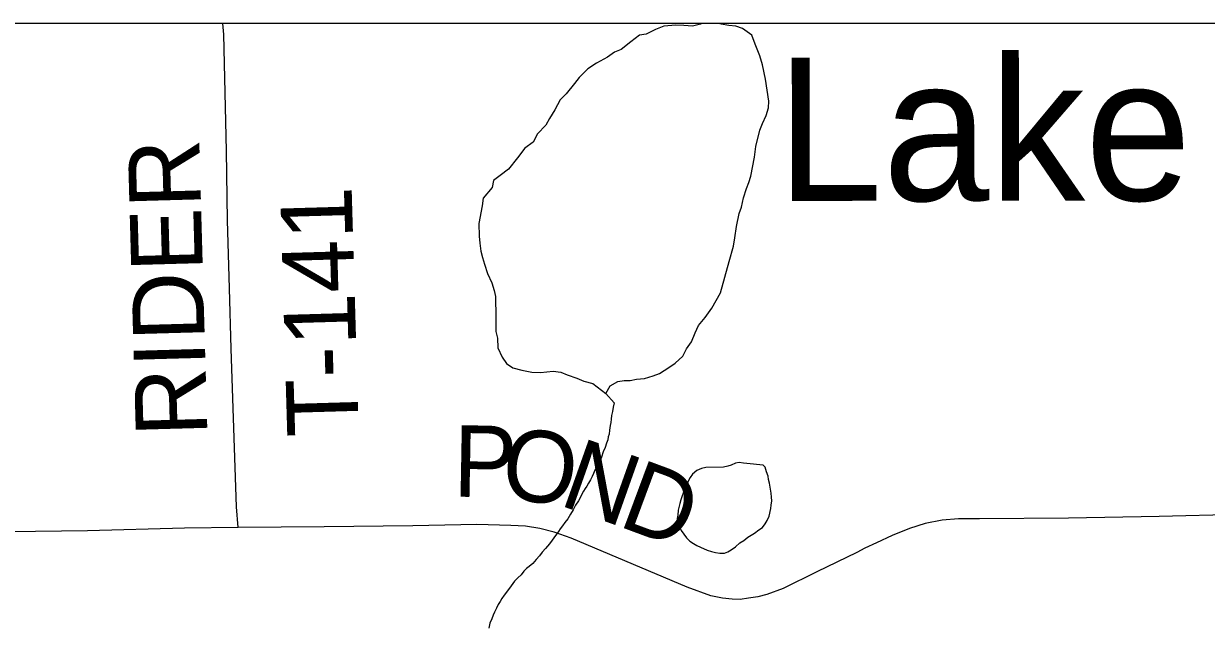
# Model space of a CAD drawing. Extents: x 0 to 34, y 0 to 22.
# Drawn here: x 4.731 to 5.67, y 20.661 to 21.138 of the extents above; entities that cross this region are included whole.
import ezdxf

# ---------------------------------------------------------------- set-up
doc = ezdxf.new("R2010")
doc.units = 0
for name, color, linetype in [('GM_X_County', 7, 'Continuous'), ('GM_X_Minor_Lake', 7, 'Continuous'), ('GM_X_Minor_Lake_Text', 7, 'Continuous'), ('GM_X_Minor_River', 7, 'Continuous'), ('GM_X_Township', 7, 'Continuous'), ('GM_X_Township_Road', 7, 'Continuous'), ('GM_X_Township_Road_Text', 7, 'Continuous')]:
    doc.layers.add(name, color=color, linetype=linetype)

msp = doc.modelspace()

# ---------------------------------------------------------------- linework, layer by layer
at = {"layer": 'GM_X_County'}
msp.add_lwpolyline([(9.16225, 14.34203), (9.16225, 21.13849), (2.36225, 21.13849), (2.36225, 14.33849), (9.00028, 14.33849)], dxfattribs=at)
at = {"layer": 'GM_X_Minor_Lake'}
for points in [[(5.26975, 21.13849), (5.26846, 21.13806), (5.26201, 21.13653), (5.25518, 21.1369), (5.24873, 21.13728), (5.23925, 21.13651), (5.2328, 21.13384), (5.22521, 21.13003), (5.2199, 21.12927), (5.21307, 21.12394), (5.20548, 21.11786), (5.20016, 21.11595), (5.19447, 21.11177), (5.18575, 21.1072), (5.17892, 21.10264), (5.17209, 21.09579), (5.16829, 21.09085), (5.16184, 21.08286), (5.15691, 21.07792), (5.15273, 21.06994), (5.14856, 21.0631), (5.14552, 21.05778), (5.13907, 21.05093), (5.13566, 21.04447), (5.12882, 21.03953), (5.12313, 21.03192), (5.11592, 21.0228), (5.10947, 21.01786), (5.10416, 21.01405), (5.10302, 21.00835), (5.09581, 20.99999), (5.09505, 20.99391), (5.09239, 20.97985), (5.09277, 20.9696), (5.09315, 20.96428), (5.09391, 20.95783), (5.09542, 20.95289), (5.09694, 20.94758), (5.09922, 20.93998), (5.10263, 20.93277), (5.10453, 20.92669), (5.10566, 20.92176), (5.10566, 20.91644), (5.10604, 20.91036), (5.10604, 20.89403), (5.10718, 20.88872), (5.10755, 20.88112), (5.11097, 20.87353), (5.11438, 20.86859), (5.11931, 20.86518), (5.12652, 20.86329), (5.13449, 20.86178), (5.14132, 20.86141), (5.15156, 20.86256), (5.15763, 20.86181), (5.16257, 20.85953), (5.17016, 20.85688), (5.17584, 20.85461), (5.18305, 20.85272), (5.1933, 20.84475)], [(5.21265, 20.85503), (5.21758, 20.85617), (5.22403, 20.85656), (5.23086, 20.85885), (5.23579, 20.86075), (5.24338, 20.86532), (5.24832, 20.86874), (5.25439, 20.87445), (5.25742, 20.88015), (5.26122, 20.88585), (5.26425, 20.89307), (5.26691, 20.89877), (5.27222, 20.90523), (5.27754, 20.91246), (5.28437, 20.92462), (5.2912, 20.94969), (5.29462, 20.96185), (5.29576, 20.96831), (5.2969, 20.97743), (5.29917, 20.98768), (5.30107, 20.99262), (5.30259, 21.00022), (5.30487, 21.00744), (5.30677, 21.01238), (5.30828, 21.01732), (5.31132, 21.03252), (5.31246, 21.04087), (5.3155, 21.05379), (5.31777, 21.05911), (5.32043, 21.06557), (5.32233, 21.07165), (5.32271, 21.07697), (5.32005, 21.09443), (5.31778, 21.10583), (5.3155, 21.11304), (5.31171, 21.12215), (5.30906, 21.12937), (5.30185, 21.13468), (5.29654, 21.13657), (5.29085, 21.13694), (5.28478, 21.13808), (5.28245, 21.13849)], [(5.1933, 20.84475), (5.19671, 20.85084), (5.20278, 20.85426), (5.20772, 20.85503), (5.21265, 20.85503)], [(5.31806, 20.7879), (5.30523, 20.78916), (5.30257, 20.7895), (5.29915, 20.78984), (5.29612, 20.78942), (5.29273, 20.78785), (5.29008, 20.78706), (5.28667, 20.78626), (5.27263, 20.78607), (5.26923, 20.78527), (5.26545, 20.7837), (5.26208, 20.78062), (5.26021, 20.77793), (5.25873, 20.77526), (5.25763, 20.77183), (5.25541, 20.76762), (5.25394, 20.76343), (5.25284, 20.76038), (5.25212, 20.75733), (5.25066, 20.752), (5.25033, 20.7482), (5.24998, 20.74553), (5.25079, 20.74213), (5.25158, 20.73948), (5.25314, 20.73608), (5.25507, 20.73307), (5.25739, 20.73007), (5.26008, 20.72744), (5.26276, 20.72558), (5.26543, 20.7241), (5.26848, 20.72262), (5.27382, 20.72041), (5.27725, 20.71932), (5.2803, 20.7186), (5.28372, 20.71789), (5.28752, 20.71794)], [(5.28752, 20.71794), (5.29016, 20.71911), (5.2928, 20.72067), (5.29618, 20.72299), (5.29956, 20.72607), (5.30295, 20.72801), (5.30595, 20.73071), (5.31123, 20.73382), (5.31461, 20.73652), (5.31762, 20.73846), (5.31987, 20.74114), (5.32135, 20.74382), (5.32283, 20.74725), (5.32427, 20.75335), (5.32462, 20.75601), (5.32495, 20.75943), (5.32491, 20.76247), (5.3245, 20.7655), (5.32326, 20.77345), (5.32247, 20.77648), (5.32205, 20.77913), (5.32087, 20.78253), (5.31969, 20.78631), (5.31806, 20.7879)]]:
    msp.add_lwpolyline(points, dxfattribs=at)
at = {"layer": 'GM_X_Minor_River'}
msp.add_lwpolyline([(5.1933, 20.84475), (5.19987, 20.83733), (5.19918, 20.8339), (5.19849, 20.83047), (5.1978, 20.82741), (5.19748, 20.82436), (5.19716, 20.8217), (5.19683, 20.81941), (5.19615, 20.8156), (5.19583, 20.81255), (5.19512, 20.81025), (5.19479, 20.80797), (5.1937, 20.80528), (5.19264, 20.80184), (5.19119, 20.79839), (5.18976, 20.79418), (5.18794, 20.79034), (5.18611, 20.78688), (5.18465, 20.78381), (5.18357, 20.78112), (5.18248, 20.77882), (5.18102, 20.77613), (5.17955, 20.77344), (5.17808, 20.77113), (5.17698, 20.7692), (5.1755, 20.76727), (5.17404, 20.7642), (5.17295, 20.7619), (5.17148, 20.75958), (5.16927, 20.75612), (5.16745, 20.75228), (5.16524, 20.74881), (5.16303, 20.74534), (5.16082, 20.74225), (5.15897, 20.73955), (5.15712, 20.73724), (5.15564, 20.7353), (5.15417, 20.73299), (5.14863, 20.72527), (5.14528, 20.72178), (5.14268, 20.71868), (5.14046, 20.71597), (5.13786, 20.71288), (5.13526, 20.70978), (5.13227, 20.70744), (5.1304, 20.70588), (5.12817, 20.70355), (5.12594, 20.70084), (5.12333, 20.6985), (5.12073, 20.69579), (5.11815, 20.69193), (5.11519, 20.68807), (5.1126, 20.68459), (5.11075, 20.68189), (5.10928, 20.67958), (5.10781, 20.67727), (5.10635, 20.6742), (5.1049, 20.67113), (5.10381, 20.66882), (5.10273, 20.66576), (5.10128, 20.66231), (5.10023, 20.65849)], dxfattribs=at)
at = {"layer": 'GM_X_Township'}
msp.add_line((9.12907, 21.13849), (4.39527, 21.13849), dxfattribs=at)
at = {"layer": 'GM_X_Township_Road'}
for points in [[(4.90122, 20.73824), (4.90001, 20.75473), (4.89832, 20.80151), (4.89589, 20.8803), (4.89444, 20.92855), (4.89274, 20.98212), (4.89201, 21.0374), (4.88983, 21.13), (4.8892, 21.13849)], [(5.69638, 20.74867), (5.63263, 20.74697), (5.56062, 20.74576), (5.48984, 20.74527), (5.47335, 20.74527), (5.46026, 20.7443), (5.44668, 20.74164), (5.43432, 20.73751), (5.4205, 20.73194), (5.40806, 20.72629), (5.39898, 20.72203), (5.39254, 20.71856), (5.36087, 20.70309), (5.33396, 20.69), (5.32111, 20.68515), (5.31383, 20.68321), (5.30656, 20.68224), (5.30002, 20.68127), (5.29347, 20.68151), (5.28596, 20.68224), (5.27674, 20.68418), (5.25783, 20.69097), (5.16571, 20.73), (5.15214, 20.73461), (5.14098, 20.73751), (5.12959, 20.73945), (5.11771, 20.73994), (5.0908, 20.74067), (5.03989, 20.7397), (4.96959, 20.73897), (4.90122, 20.73824), (4.8588, 20.73776), (4.78171, 20.73582), (4.71965, 20.73485)]]:
    msp.add_lwpolyline(points, dxfattribs=at)

# ---------------------------------------------------------------- texts
at = {"layer": 'GM_X_Minor_Lake_Text'}
msp.add_text('Lake', height=0.113703, rotation=0.0635, dxfattribs=at).set_placement((5.32857, 20.99771))
at = {"layer": 'GM_X_Township_Road_Text'}
for s, height, rotation, p in [('RIDER', 0.056818, 91.60329, (4.87698, 20.8113)), ('T-141', 0.056818, 91.67044, (4.99717, 20.81134)), ('P', 0.05682, 358.99266, (5.07168, 20.76288)), ('O', 0.05682, 352.58807, (5.10833, 20.76233)), ('N', 0.05682, 340.466, (5.15483, 20.75662)), ('D', 0.05682, 339.60981, (5.20174, 20.73998))]:
    msp.add_text(s, height=height, rotation=rotation, dxfattribs=at).set_placement(p)

doc.saveas('drawing.dxf')
